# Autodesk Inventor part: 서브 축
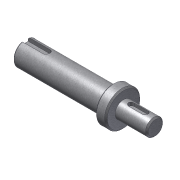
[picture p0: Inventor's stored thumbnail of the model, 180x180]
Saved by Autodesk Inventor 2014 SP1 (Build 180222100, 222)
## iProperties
Created: 2012-07
Part Number: 서브 축
Document SubType Name: Modeling
Designer: SeoGD™ [www.esajin.kr]
Density: 1 g/cm^3
Material: 일반
Appearance: 금속-강(스테인리스, 브러시됨)
Author: SeoGD™ [www.esajin.kr]
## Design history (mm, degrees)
sketch "스케치1"
  geometry: L1 (0, 0)-(-92.5, 0); L2 (0, 0)-(0, -6); L3 (0, -6)-(-22.5, -6); L4 (-22.5, -12.5)-(-30.169, -12.5); L5 (-30.169, -8.5)-(-92.5, -8.5); L6 (-92.5, -8.5)-(-92.5, 0); L7 (-30.169, -8.5)-(-30.169, -12.5); L8 (-22.5, -6)-(-22.5, -12.5); L9 (-30.169, 20)-(-30.169, -20) reference; 1 further point
  constraints: 17 end point, 3 parallel, 3 perpendicular, 1 coincident, 1 collinear, 1 horizontal
  dimensions: "d1" = 12 diameter of L3 L1; "d2" = 25 diameter of L4 L1; "d3" = 17 diameter of L5 L1; "d4" = 62.33128 distance of L5.start L5.end (derived); "d18" = 22.5 distance of L2.end L3.end; "d20" = 70 distance between parallel lines of L6 L8
revolve "회전1" sketch "스케치1" stored, may be unused: angle "d5" = 90 deg
chamfer "모따기1" distance "d6" = 1; stored, may be unused: second distance "d7" = 2, angle "d8" = 45 deg
node "작업 평면1"
sketch "스케치2"
  geometry: L1 (11.25, 5)-(11.25, -5) reference; L2 (-5.75, -2)-(4.25, -2); L3 (4.25, 2)-(-5.75, 2); A1 r 2 centre (4.25, 0) between (4.25, -2) and (4.25, 2); A2 r 2 centre (-5.75, 0) between (-5.75, 2) and (-5.75, -2); 2 further points
  constraints: 4 end point, 4 point on circle, 4 tangent, 2 centre point, 1 horizontal alignment, 1 midpoint, 1 parallel, 1 perpendicular
  dimensions: "d9" = 4 distance between parallel lines of L2 L3; "d10" = 14 dimension on A1 A2; "d11" = 5 distance edge to line of A1 L1
extrude "돌출1" cut sketch "스케치2" distance "d12" = 2.5; taper "d13" = 0 deg
node "작업 평면2"
sketch "스케치3"
  geometry: L1 (-31.166, -7.5)-(-31.166, 7.5) reference; L2 (-31.166, 2.5)-(-15.666, 2.5); L3 (-15.666, -2.5)-(-31.166, -2.5); A1 r 2.5 centre (-15.666, 0) between (-15.666, -2.5) and (-15.666, 2.5); 2 further points
  constraints: 4 end point, 2 perpendicular, 2 point on circle, 2 point on line, 2 tangent, 1 centre point, 1 horizontal alignment, 1 midpoint
  dimensions: "d14" = 5 distance between parallel lines of L3 L2; "d15" = 18 dimension on A1 L1
extrude "돌출2" cut sketch "스케치3" distance "d16" = 3; taper "d17" = 0 deg
node "솔리드1"
node "참조5"
